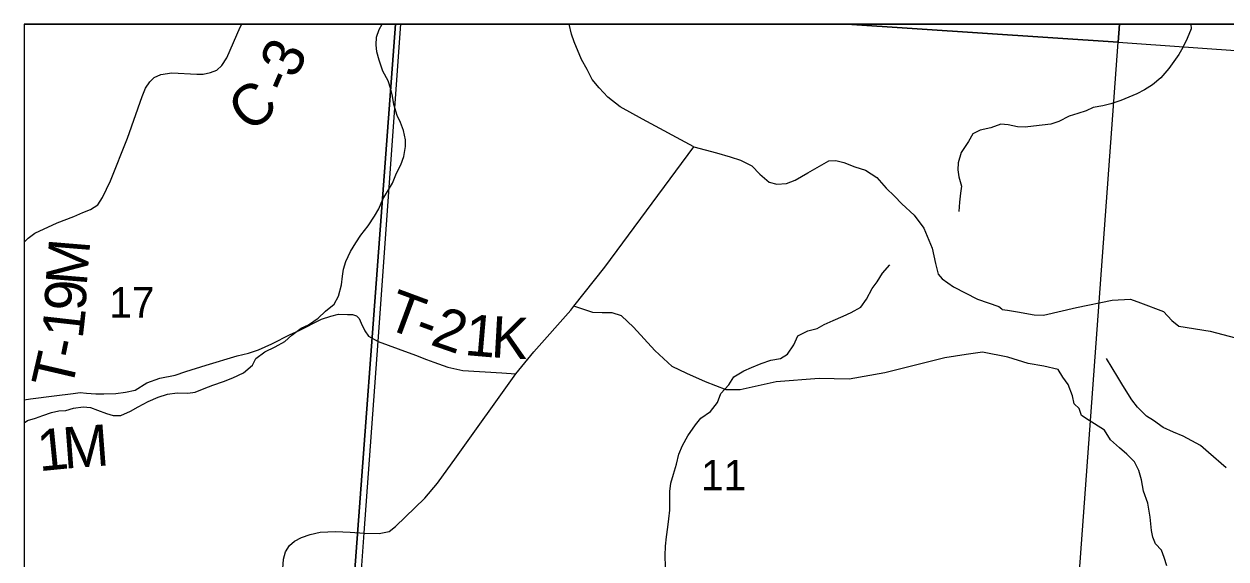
# Model space of a CAD drawing. Extents: x -8.2 to 34, y 0 to 22.
# Drawn here: x 2.1 to 3.755, y 20.164 to 20.9 of the extents above; entities that cross this region are included whole.
import ezdxf

# ---------------------------------------------------------------- set-up
doc = ezdxf.new("R2010")
doc.units = 0
for name, color, linetype in [('GM_X_Corporation', 7, 'Continuous'), ('GM_X_County_Road', 7, 'Continuous'), ('GM_X_County_Road_Text', 7, 'Continuous'), ('GM_X_Minor_River', 7, 'Continuous'), ('GM_X_Section_Text', 7, 'Continuous'), ('GM_X_Township_Road', 7, 'Continuous'), ('GM_X_Township_Road_Text', 7, 'Continuous'), ('GM_X_Township_Text', 7, 'Continuous'), ('SH_Data', 7, 'Continuous')]:
    doc.layers.add(name, color=color, linetype=linetype)

msp = doc.modelspace()

# ---------------------------------------------------------------- linework, layer by layer
at = {"layer": 'GM_X_Corporation'}
msp.add_lwpolyline([(6.4774, 18.0203), (6.488, 18.1752), (6.5242, 18.7061), (6.5297, 18.7882), (6.5448, 18.981), (6.5455, 18.9878), (6.5461, 19.0017), (6.5463, 19.009), (6.5469, 19.0218), (6.548, 19.0467), (6.5487, 19.0617), (6.5495, 19.0821), (6.5503, 19.0966), (6.5514, 19.1092), (6.5523, 19.118), (6.5529, 19.1264), (6.5537, 19.1382), (6.5541, 19.1447), (6.5536, 19.1514), (6.5814, 19.5334), (6.6608, 20.6695), (6.6768, 20.9), (2.1, 20.9), (2.1, 14.1)], dxfattribs=at)
for points in [[(2.6112, 20.9), (2.1, 20.9), (2.1, 19.9409), (2.5373, 19.9092)], [(3.2326, 20.9), (2.6112, 20.9), (2.5373, 19.9092), (3.5308, 19.8461), (3.6063, 20.8752)], [(3.608, 20.9), (3.2326, 20.9), (3.6063, 20.8752)], [(4.614, 20.9), (3.608, 20.9), (3.6063, 20.8752), (4.607, 20.8038)], [(4.607, 20.8038), (4.5379, 19.7849), (3.5308, 19.8461), (3.6063, 20.8752)]]:
    msp.add_lwpolyline(points, close=True, dxfattribs=at)
at = {"layer": 'GM_X_County_Road'}
for points in [[(2.1, 20.6001), (2.1056, 20.6054), (2.1147, 20.6125), (2.1457, 20.6266), (2.1684, 20.6354), (2.181, 20.6407), (2.1915, 20.6447), (2.2017, 20.6512), (2.2082, 20.6612), (2.2189, 20.6841), (2.2425, 20.7428), (2.2626, 20.8005), (2.2671, 20.8119), (2.2732, 20.8207), (2.2793, 20.8267), (2.2883, 20.8308), (2.3034, 20.8327), (2.3379, 20.831), (2.3468, 20.8312), (2.3565, 20.8334), (2.3656, 20.8365), (2.3721, 20.8429), (2.3792, 20.8537), (2.3976, 20.8956), (2.3998, 20.9)], [(2.5491, 20.2008), (2.5685, 20.1996), (2.5891, 20.1992), (2.6027, 20.2019), (2.6114, 20.2089), (2.6517, 20.2476), (2.6692, 20.2683), (2.6953, 20.3047), (2.7771, 20.419), (2.8019, 20.4492), (2.8527, 20.5063), (2.857, 20.5119), (2.8996, 20.5657), (3.022, 20.731), (2.9512, 20.769), (2.9206, 20.7862), (2.9035, 20.7995), (2.8918, 20.8122), (2.8822, 20.8236), (2.8751, 20.8377), (2.8672, 20.8513), (2.8574, 20.8754), (2.8538, 20.8863), (2.8505, 20.9)], [(2.54, 19.9286), (2.5395, 19.9394), (2.5363, 19.9525), (2.5262, 19.9731), (2.5074, 20.0097), (2.4852, 20.0546), (2.4727, 20.0797), (2.4618, 20.1034), (2.4574, 20.1204), (2.4552, 20.1365), (2.4562, 20.1505), (2.4574, 20.1639), (2.4601, 20.1737), (2.4653, 20.1828), (2.4721, 20.1885), (2.4819, 20.1935), (2.4937, 20.1976), (2.5078, 20.2011), (2.5287, 20.2021), (2.5491, 20.2008)]]:
    msp.add_lwpolyline(points, dxfattribs=at)
at = {"layer": 'GM_X_Minor_River'}
for points in [[(2.1, 20.3513), (2.1047, 20.3545), (2.1157, 20.3579), (2.1259, 20.3613), (2.138, 20.3655), (2.1479, 20.3678), (2.1577, 20.3685), (2.1679, 20.3716), (2.1812, 20.3735), (2.1914, 20.3724), (2.2009, 20.3689), (2.2134, 20.3644), (2.2228, 20.3614), (2.2334, 20.3614), (2.2467, 20.3675), (2.2569, 20.3735), (2.2709, 20.3807), (2.2845, 20.3868), (2.2974, 20.391), (2.3107, 20.3925), (2.3254, 20.3921), (2.3356, 20.3937), (2.3481, 20.3986), (2.3599, 20.4032), (2.3746, 20.4081), (2.3875, 20.4134), (2.4023, 20.4203), (2.4144, 20.4305), (2.4189, 20.44), (2.4314, 20.4491), (2.4458, 20.4559), (2.459, 20.4635), (2.4688, 20.4719), (2.4817, 20.4814), (2.4915, 20.4863), (2.5048, 20.4954), (2.515, 20.5049), (2.5267, 20.5148), (2.5331, 20.5258), (2.5369, 20.5413), (2.5384, 20.5531), (2.5399, 20.5629), (2.5429, 20.5732), (2.5494, 20.5869), (2.5569, 20.599), (2.5637, 20.6096), (2.5739, 20.6225), (2.5826, 20.6358), (2.5883, 20.646), (2.594, 20.6589), (2.6015, 20.6718), (2.6072, 20.6813), (2.6129, 20.695), (2.6189, 20.7064), (2.623, 20.7178), (2.6249, 20.7314), (2.6253, 20.7409), (2.6226, 20.7534), (2.6181, 20.7644), (2.6135, 20.7743), (2.609, 20.7891), (2.6074, 20.8008), (2.6048, 20.8103), (2.6013, 20.8217), (2.5941, 20.8353), (2.5888, 20.8501), (2.5858, 20.8619), (2.5846, 20.8714), (2.5854, 20.882), (2.5888, 20.8926), (2.5931, 20.9)], [(3.7062, 20.9), (3.7069, 20.8935), (3.7013, 20.8803), (3.6952, 20.8677), (3.6896, 20.8579), (3.676, 20.8389), (3.665, 20.826), (3.6533, 20.8165), (3.6423, 20.8093), (3.6317, 20.804), (3.6211, 20.7994), (3.6097, 20.7949), (3.5961, 20.7903), (3.5851, 20.7877), (3.5719, 20.785), (3.562, 20.7808), (3.5507, 20.777), (3.5386, 20.7732), (3.5246, 20.766), (3.5136, 20.7622), (3.4898, 20.7595), (3.478, 20.758), (3.4678, 20.7588), (3.4549, 20.7614), (3.4447, 20.7622), (3.4311, 20.7572), (3.4163, 20.7542), (3.4061, 20.7489), (3.4, 20.7382), (3.3902, 20.7234), (3.3861, 20.709), (3.3853, 20.6995), (3.3868, 20.6897), (3.3903, 20.6768), (3.3891, 20.6673), (3.3876, 20.6548), (3.3869, 20.6423)], [(2.983, 20.1535), (2.9826, 20.1687), (2.983, 20.1819), (2.9845, 20.1944), (2.9864, 20.2077), (2.9875, 20.2191), (2.989, 20.2312), (2.989, 20.2567), (2.9905, 20.2684), (2.9939, 20.2809), (2.998, 20.2946), (3.0014, 20.3083), (3.0063, 20.32), (3.0139, 20.3337), (3.0245, 20.3485), (3.0317, 20.358), (3.0449, 20.3671), (3.0544, 20.3792), (3.0593, 20.3917), (3.0702, 20.4035), (3.077, 20.4145), (3.0907, 20.4229), (3.1013, 20.4274), (3.1149, 20.4331), (3.1281, 20.4377), (3.1414, 20.44), (3.1512, 20.4457), (3.1599, 20.4586), (3.1652, 20.4711), (3.1788, 20.4779), (3.1917, 20.4813), (3.2015, 20.4866), (3.214, 20.492), (3.2276, 20.498), (3.2386, 20.5034), (3.2519, 20.5106), (3.2598, 20.5216), (3.2677, 20.536), (3.2742, 20.5455), (3.2817, 20.5572), (3.2919, 20.5686)], [(3.755, 20.2893), (3.7307, 20.3105), (3.7197, 20.32), (3.6955, 20.3329), (3.6822, 20.3386), (3.6682, 20.345), (3.6549, 20.3545), (3.6451, 20.3606), (3.6329, 20.3731), (3.625, 20.3829), (3.6174, 20.3954), (3.6113, 20.4049), (3.6056, 20.4144), (3.5977, 20.4269), (3.5901, 20.4398)]]:
    msp.add_lwpolyline(points, dxfattribs=at)
at = {"layer": 'GM_X_Township_Road'}
for points in [[(3.022, 20.731), (3.0531, 20.7227), (3.0721, 20.7174), (3.0861, 20.7128), (3.1017, 20.7048), (3.1128, 20.6937), (3.1258, 20.6826), (3.1365, 20.6797), (3.1497, 20.6807), (3.1616, 20.6851), (3.1789, 20.6953), (3.2079, 20.712), (3.2173, 20.7124), (3.2287, 20.7095), (3.2439, 20.7038), (3.2585, 20.6988), (3.2739, 20.6888), (3.2869, 20.6742), (3.2984, 20.6632), (3.3083, 20.6525), (3.3252, 20.6373), (3.3388, 20.619), (3.3503, 20.5916), (3.3546, 20.5704), (3.3586, 20.5557), (3.3639, 20.5495), (3.3797, 20.5384), (3.4124, 20.5217), (3.442, 20.5116), (3.4459, 20.5081)], [(3.4459, 20.5081), (3.4467, 20.5074), (3.4538, 20.5063), (3.4674, 20.5042), (3.4906, 20.4999), (3.5036, 20.4997), (3.549, 20.51), (3.598, 20.52), (3.6233, 20.5213), (3.6371, 20.5165), (3.6684, 20.5044), (3.6799, 20.4923), (3.6898, 20.4846), (3.7328, 20.4774), (3.7766, 20.4661)], [(2.1, 20.3831), (2.1091, 20.3842), (2.1417, 20.3884), (2.1678, 20.3919), (2.1771, 20.3931), (2.1858, 20.3921), (2.1988, 20.3915), (2.21, 20.3915), (2.2265, 20.3919), (2.2398, 20.3938), (2.2528, 20.3962), (2.2691, 20.4064), (2.2871, 20.4128), (2.3082, 20.4169), (2.3227, 20.4219), (2.3508, 20.4306), (2.3934, 20.4434), (2.4092, 20.4471), (2.4228, 20.4517), (2.4412, 20.4601), (2.4662, 20.473), (2.4787, 20.4786), (2.5093, 20.4939), (2.5223, 20.4982), (2.5328, 20.5007), (2.5452, 20.5003), (2.5521, 20.5003), (2.5577, 20.4986), (2.5614, 20.4949), (2.5641, 20.4887), (2.5692, 20.4781), (2.574, 20.4705), (2.5875, 20.4634)], [(3.6732, 20.1548), (3.6697, 20.1659), (3.6659, 20.1764), (3.6577, 20.1847), (3.6539, 20.1939), (3.6523, 20.2034), (3.6504, 20.2218), (3.6472, 20.241), (3.6412, 20.2572), (3.6384, 20.2729), (3.6347, 20.2857), (3.6289, 20.2978), (3.6181, 20.3081), (3.6078, 20.3172), (3.5955, 20.3281), (3.5874, 20.3413), (3.5736, 20.3498), (3.5661, 20.3548), (3.5559, 20.3617), (3.5525, 20.3709), (3.5458, 20.3773), (3.5432, 20.3884), (3.5373, 20.4039), (3.5302, 20.4144), (3.5236, 20.4249), (3.5039, 20.4293), (3.4823, 20.4332), (3.4544, 20.4415), (3.4195, 20.4487), (3.3969, 20.4452), (3.3674, 20.4408), (3.3509, 20.4366), (3.2849, 20.4201), (3.2357, 20.4113), (3.1945, 20.4125), (3.1355, 20.4076), (3.0859, 20.3968), (3.0666, 20.3968), (3.0383, 20.4079), (3.0126, 20.4193), (2.992, 20.4289), (2.9685, 20.4509), (2.939, 20.4831), (2.9225, 20.4987), (2.9098, 20.5028), (2.8958, 20.5025), (2.8831, 20.5034), (2.8666, 20.5088), (2.857, 20.5119)], [(2.5875, 20.4634), (2.6152, 20.4533), (2.6387, 20.4444), (2.654, 20.4387), (2.664, 20.4349), (2.6832, 20.4279), (2.7041, 20.4235), (2.7578, 20.42), (2.7771, 20.419)]]:
    msp.add_lwpolyline(points, dxfattribs=at)
at = {"layer": 'GM_X_Township_Text'}
msp.add_lwpolyline([(2.227, 15.7788), (2.2908, 16.5825), (2.3045, 16.7554), (2.3047, 16.7573), (2.3109, 16.8355), (2.3177, 16.9219), (2.3436, 17.248), (2.3535, 17.3723), (2.3875, 17.8009), (2.3895, 17.8266), (2.4044, 18.0138), (2.4049, 18.02), (2.4177, 18.1814), (2.4336, 18.4736), (2.4376, 18.5459), (2.4377, 18.5489), (2.4735, 18.885), (2.5013, 19.2713), (2.5435, 19.8534), (2.5683, 20.2001), (2.5873, 20.4639), (2.6187, 20.9)], dxfattribs=at)
at = {"layer": 'SH_Data'}
for q in [(2.1, 14.1), (8.9, 20.9)]:
    msp.add_line((2.1, 20.9), q, dxfattribs=at)

# ---------------------------------------------------------------- texts
at = {"layer": 'GM_X_County_Road_Text'}
for s, rotation, p in [('3', 64.5219, (2.4734, 20.8231)), ('-', 66.7817, (2.4644, 20.8022)), ('C', 39.5937, (2.411, 20.7491))]:
    msp.add_text(s, height=0.0568, rotation=rotation, dxfattribs=at).set_placement(p)
at = {"layer": 'GM_X_Section_Text'}
for s, p in [('17', (2.2173, 20.4962)), ('11', (3.0319, 20.2585))]:
    msp.add_text(s, height=0.04186, rotation=0, dxfattribs=at).set_placement(p)
at = {"layer": 'GM_X_Township_Road_Text'}
for s, rotation, p in [('M', 85.3273, (2.1862, 20.5389)), ('9', 87.6977, (2.1848, 20.5048)), ('T', 339.6573, (2.5949, 20.4827)), ('1', 83.6062, (2.1806, 20.4659)), ('2', 340.9058, (2.6577, 20.4594)), ('-', 339.5216, (2.6346, 20.468)), ('1', 355.0606, (2.7054, 20.4448)), ('K', 356.8172, (2.7419, 20.4417)), ('T', 76.902, (2.1651, 20.3948)), ('-', 78.2839, (2.175, 20.4376)), ('1', 5.723, (2.121, 20.2847)), ('M', 4.4021, (2.1554, 20.2882))]:
    msp.add_text(s, height=0.0568, rotation=rotation, dxfattribs=at).set_placement(p)

doc.saveas('drawing.dxf')
